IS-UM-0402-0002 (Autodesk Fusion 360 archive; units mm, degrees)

design "IS-UM-0402-0002" references "6 holes POWER", "LED", "3M Screw", "4 ports Ethernet", "SFP SLOT", "Digitus_DN-651107_LAN-Switch"
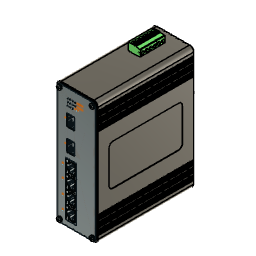
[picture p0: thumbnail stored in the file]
sketch "Sketch1" plane through (0, 0, 0) normal (0, 1, 0) x axis (1, 0, 0)
  line L1 (45, 0) -> (5, 0)
  line L2 (50, -145) -> (50, -5)
  line L3 (5, -150) -> (45, -150)
  line L4 (0, -5) -> (0, -145)
  arc A1 centre (5, -145) radius 5 clockwise from (5, -150) to (0, -145)
  arc A2 centre (45, -145) radius 5 clockwise from (50, -145) to (45, -150)
  arc A3 centre (5, -5) radius 5 clockwise from (0, -5) to (5, 0)
  arc A4 centre (45, -5) radius 5 clockwise from (45, 0) to (50, -5)
  point P1 (0, 0)
  point P2 (0, 0)
  point P4 (0, -150)
  point P3 (50, 0)
  horizontal L1
  vertical L2
  horizontal L3
  vertical L4
  coincident P1 P2
  coincident P4 L3
  coincident P4 L4
  tangent L3 A1
  tangent L4 A1
  tangent L2 A2
  tangent L3 A2
  equal A1 A2
  coincident P2 L1
  coincident P2 L4
  tangent L1 A3
  tangent L4 A3
  equal A1 A3
  coincident P3 L1
  coincident P3 L2
  tangent L1 A4
  tangent L2 A4
  equal A1 A4
  dimension "d1" distance P2 P3 = 50
  dimension "d2" distance P2 P4 = 150
  dimension "d3" radius A1 = 5
extrude "Extrude1" new body sketch "Sketch1" along normal blind 120
sketch "Sketch2" plane through (0, 0, 0) normal (0, -1, 0) x axis (1, 0, 0)
  line L1 (5, 150) -> (45, 150)
  line L2 (0, 5) -> (0, 145)
  line L3 (45, 0) -> (5, 0)
  line L4 (50, 145) -> (50, 5)
  line L5 (45, 1.5) -> (5, 1.5)
  line L6 (48.5, 145) -> (48.5, 5)
  line L7 (5, 148.5) -> (45, 148.5)
  line L8 (1.5, 5) -> (1.5, 145)
  line L9 (45, 0) -> (5, 0)
  line L10 (50, 145) -> (50, 5)
  line L11 (5, 150) -> (45, 150)
  line L12 (0, 5) -> (0, 145)
  arc A1 centre (45, 145) radius 5 clockwise from (45, 150) to (50, 145)
  arc A2 centre (5, 145) radius 5 clockwise from (0, 145) to (5, 150)
  arc A3 centre (5, 5) radius 5 clockwise from (5, 0) to (0, 5)
  arc A4 centre (45, 5) radius 5 clockwise from (50, 5) to (45, 0)
  arc A5 centre (45, 5) radius 3.5 clockwise from (48.5, 5) to (45, 1.5)
  arc A6 centre (45, 145) radius 3.5 clockwise from (45, 148.5) to (48.5, 145)
  arc A7 centre (5, 145) radius 3.5 clockwise from (1.5, 145) to (5, 148.5)
  arc A8 centre (5, 5) radius 3.5 clockwise from (5, 1.5) to (1.5, 5)
  arc A9 centre (45, 5) radius 5 clockwise from (50, 5) to (45, 0)
  arc A10 centre (45, 145) radius 5 clockwise from (45, 150) to (50, 145)
  arc A11 centre (5, 145) radius 5 clockwise from (0, 145) to (5, 150)
  arc A12 centre (5, 5) radius 5 clockwise from (5, 0) to (0, 5)
  dimension "d6" = -1.5
  dimension "d7" distance L3 = 0
extrude "Extrude2" cut sketch "Sketch2" against normal blind 1.5
sketch "Sketch3" plane through (0, 120, 0) normal (0, 1, 0) x axis (-1, 0, 0)
  line L1 (-50, 5) -> (-50, 145)
  line L2 (-5, 0) -> (-45, 0)
  line L3 (0, 145) -> (0, 5)
  line L4 (-45, 150) -> (-5, 150)
  line L5 (-5, 1.5) -> (-45, 1.5)
  line L6 (-1.5, 145) -> (-1.5, 5)
  line L7 (-45, 148.5) -> (-5, 148.5)
  line L8 (-48.5, 5) -> (-48.5, 145)
  line L9 (-5, 0) -> (-45, 0)
  line L10 (0, 145) -> (0, 5)
  line L11 (-45, 150) -> (-5, 150)
  line L12 (-50, 5) -> (-50, 145)
  arc A1 centre (-45, 145) radius 5 clockwise from (-50, 145) to (-45, 150)
  arc A2 centre (-45, 5) radius 5 clockwise from (-45, 0) to (-50, 5)
  arc A3 centre (-5, 5) radius 5 clockwise from (0, 5) to (-5, 0)
  arc A4 centre (-5, 145) radius 5 clockwise from (-5, 150) to (0, 145)
  arc A5 centre (-5, 5) radius 3.5 clockwise from (-1.5, 5) to (-5, 1.5)
  arc A6 centre (-5, 145) radius 3.5 clockwise from (-5, 148.5) to (-1.5, 145)
  arc A7 centre (-45, 145) radius 3.5 clockwise from (-48.5, 145) to (-45, 148.5)
  arc A8 centre (-45, 5) radius 3.5 clockwise from (-45, 1.5) to (-48.5, 5)
  arc A9 centre (-5, 5) radius 5 clockwise from (0, 5) to (-5, 0)
  arc A10 centre (-5, 145) radius 5 clockwise from (-5, 150) to (0, 145)
  arc A11 centre (-45, 145) radius 5 clockwise from (-50, 145) to (-45, 150)
  arc A12 centre (-45, 5) radius 5 clockwise from (-45, 0) to (-50, 5)
  dimension "d10" = -1.5
  dimension "d11" distance L2 = 0
extrude "Extrude3" cut sketch "Sketch3" against normal blind 1.5
sketch "Sketch4" plane through (0, 1.5, 0) normal (0, -1, 0) x axis (1, 0, 0)
  line L1 (1.5, 145) -> (1.5, 5)
  line L2 (45, 148.5) -> (5, 148.5)
  line L3 (48.5, 5) -> (48.5, 145)
  line L4 (5, 1.5) -> (45, 1.5)
  line L5 (45, 0) -> (5, 0)
  line L6 (50, 145) -> (50, 5)
  line L7 (5, 150) -> (45, 150)
  line L8 (0, 5) -> (0, 145)
  line L9 (25, 75) -> (25, 148.5)
  line L10 (25, 75) -> (1.5, 75)
  line L11 (0.75, 9) -> (0, 9)
  line L12 (0.75, 10.5) -> (0.75, 9)
  line L13 (0, 10.5) -> (0.75, 10.5)
  line L14 (0, 9) -> (0, 10.5)
  line L15 (0, 12.75) -> (0.75, 12.75)
  line L16 (0, 11.25) -> (0, 12.75)
  line L17 (0.75, 11.25) -> (0, 11.25)
  line L18 (0.75, 12.75) -> (0.75, 11.25)
  line L19 (0, 15) -> (0.75, 15)
  line L20 (0, 13.5) -> (0, 15)
  line L21 (0.75, 13.5) -> (0, 13.5)
  line L22 (0.75, 15) -> (0.75, 13.5)
  line L23 (0.75, 19.25) -> (0, 19.25)
  line L24 (0.75, 20.75) -> (0.75, 19.25)
  line L25 (0, 19.25) -> (0, 20.75)
  line L26 (0.75, 18.5) -> (0.75, 17)
  line L27 (0, 21.5) -> (0, 23)
  line L28 (0, 23) -> (0.75, 23)
  line L29 (0.75, 21.5) -> (0, 21.5)
  line L30 (0, 20.75) -> (0.75, 20.75)
  line L31 (0, 18.5) -> (0.75, 18.5)
  line L32 (0, 17) -> (0, 18.5)
  line L33 (0.75, 17) -> (0, 17)
  line L34 (0.75, 23) -> (0.75, 21.5)
  line L35 (0.75, 27.25) -> (0, 27.25)
  line L36 (0.75, 28.75) -> (0.75, 27.25)
  line L37 (0, 27.25) -> (0, 28.75)
  line L38 (0.75, 26.5) -> (0.75, 25)
  line L39 (0, 29.5) -> (0, 31)
  line L40 (0, 31) -> (0.75, 31)
  line L41 (0.75, 29.5) -> (0, 29.5)
  line L42 (0, 28.75) -> (0.75, 28.75)
  line L43 (0, 26.5) -> (0.75, 26.5)
  line L44 (0, 25) -> (0, 26.5)
  line L45 (0.75, 25) -> (0, 25)
  line L46 (0.75, 31) -> (0.75, 29.5)
  line L47 (0.75, 141) -> (0, 141)
  line L48 (0, 138.75) -> (0, 137.25)
  line L49 (0, 133) -> (0, 131.5)
  line L50 (0, 120.5) -> (0, 119)
  line L51 (0, 128.5) -> (0, 127)
  line L52 (0, 121.25) -> (0.75, 121.25)
  line L53 (0.75, 125) -> (0, 125)
  line L54 (0.75, 128.5) -> (0, 128.5)
  line L55 (0.75, 129.25) -> (0.75, 130.75)
  line L56 (0.75, 120.5) -> (0, 120.5)
  line L57 (0.75, 131.5) -> (0.75, 133)
  line L58 (0.75, 123.5) -> (0.75, 125)
  line L59 (0, 122.75) -> (0, 121.25)
  line L60 (0.75, 138.75) -> (0, 138.75)
  line L61 (0, 130.75) -> (0, 129.25)
  line L62 (0.75, 130.75) -> (0, 130.75)
  line L63 (0, 139.5) -> (0.75, 139.5)
  line L64 (0.75, 133) -> (0, 133)
  line L65 (0.75, 127) -> (0.75, 128.5)
  line L66 (0.75, 137.25) -> (0.75, 138.75)
  line L67 (0, 137.25) -> (0.75, 137.25)
  line L68 (0.75, 119) -> (0.75, 120.5)
  line L69 (0, 125) -> (0, 123.5)
  line L70 (0.75, 122.75) -> (0, 122.75)
  line L71 (0.75, 139.5) -> (0.75, 141)
  line L72 (0, 129.25) -> (0.75, 129.25)
  line L73 (0, 123.5) -> (0.75, 123.5)
  line L74 (0, 119) -> (0.75, 119)
  line L75 (0, 141) -> (0, 139.5)
  line L76 (0.75, 135) -> (0.75, 136.5)
  line L77 (0.75, 136.5) -> (0, 136.5)
  line L78 (0, 136.5) -> (0, 135)
  line L79 (0, 131.5) -> (0.75, 131.5)
  line L80 (0, 135) -> (0.75, 135)
  line L81 (0.75, 121.25) -> (0.75, 122.75)
  line L82 (0, 127) -> (0.75, 127)
  line L83 (49.25, 127) -> (49.25, 128.5)
  line L84 (50, 122.75) -> (50, 121.25)
  line L85 (49.25, 121.25) -> (49.25, 122.75)
  line L86 (50, 127) -> (49.25, 127)
  line L87 (49.25, 129.25) -> (49.25, 130.75)
  line L88 (49.25, 137.25) -> (49.25, 138.75)
  line L89 (50, 119) -> (49.25, 119)
  line L90 (50, 139.5) -> (49.25, 139.5)
  line L91 (50, 123.5) -> (49.25, 123.5)
  line L92 (50, 136.5) -> (50, 135)
  line L93 (50, 135) -> (49.25, 135)
  line L94 (50, 120.5) -> (50, 119)
  line L95 (50, 133) -> (50, 131.5)
  line L96 (49.25, 119) -> (49.25, 120.5)
  line L97 (50, 128.5) -> (50, 127)
  line L98 (49.25, 131.5) -> (49.25, 133)
  line L99 (49.25, 120.5) -> (50, 120.5)
  line L100 (49.25, 133) -> (50, 133)
  line L101 (50, 138.75) -> (50, 137.25)
  line L102 (50, 125) -> (50, 123.5)
  line L103 (49.25, 139.5) -> (49.25, 141)
  line L104 (49.25, 135) -> (49.25, 136.5)
  line L105 (49.25, 136.5) -> (50, 136.5)
  line L106 (50, 137.25) -> (49.25, 137.25)
  line L107 (49.25, 125) -> (50, 125)
  line L108 (50, 121.25) -> (49.25, 121.25)
  line L109 (49.25, 138.75) -> (50, 138.75)
  line L110 (50, 130.75) -> (50, 129.25)
  line L111 (49.25, 141) -> (50, 141)
  line L112 (49.25, 130.75) -> (50, 130.75)
  line L113 (50, 129.25) -> (49.25, 129.25)
  line L114 (50, 131.5) -> (49.25, 131.5)
  line L115 (49.25, 122.75) -> (50, 122.75)
  line L116 (50, 141) -> (50, 139.5)
  line L117 (49.25, 128.5) -> (50, 128.5)
  line L118 (49.25, 123.5) -> (49.25, 125)
  line L119 (50, 18.5) -> (49.25, 18.5)
  line L120 (49.25, 19.25) -> (50, 19.25)
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  point P22 (25, 148.5)
  point P23 (1.5, 75)
  point P25 (0, 9)
  point P74 (0, 141)
  point P26 (0.75, 9)
  point P81 (0.75, 141)
  point P27 (0.75, 10.5)
  point P77 (0.75, 139.5)
  point P28 (0, 10.5)
  point P69 (0, 139.5)
  point P29 (0.75, 12.75)
  point P67 (0.75, 137.25)
  point P30 (0, 12.75)
  point P68 (0, 137.25)
  point P31 (0, 11.25)
  point P89 (0, 138.75)
  point P32 (0.75, 11.25)
  point P86 (0.75, 138.75)
  point P33 (0.75, 15)
  point P79 (0.75, 135)
  point P34 (0, 15)
  point P94 (0, 135)
  point P35 (0, 13.5)
  point P90 (0, 136.5)
  point P36 (0.75, 13.5)
  point P65 (0.75, 136.5)
  point P37 (0.75, 17)
  point P95 (0.75, 133)
  point P38 (0, 19.25)
  point P96 (0, 130.75)
  point P39 (0.75, 19.25)
  point P75 (0.75, 130.75)
  point P40 (0.75, 20.75)
  point P72 (0.75, 129.25)
  point P41 (0.75, 23)
  point P73 (0.75, 127)
  point P42 (0, 20.75)
  point P62 (0, 129.25)
  point P43 (0, 23)
  point P61 (0, 127)
  point P44 (0.75, 18.5)
  point P63 (0.75, 131.5)
  point P45 (0, 21.5)
  point P66 (0, 128.5)
  point P46 (0, 17)
  point P70 (0, 133)
  point P47 (0.75, 21.5)
  point P91 (0.75, 128.5)
  point P48 (0, 18.5)
  point P84 (0, 131.5)
  point P49 (0.75, 25)
  point P83 (0.75, 125)
  point P50 (0, 27.25)
  point P76 (0, 122.75)
  point P51 (0.75, 27.25)
  point P78 (0.75, 122.75)
  point P52 (0.75, 28.75)
  point P88 (0.75, 121.25)
  point P53 (0.75, 31)
  point P87 (0.75, 119)
  point P54 (0, 28.75)
  point P82 (0, 121.25)
  point P55 (0, 31)
  point P80 (0, 119)
  point P56 (0.75, 26.5)
  point P85 (0.75, 123.5)
  point P57 (0, 29.5)
  point P93 (0, 120.5)
  point P58 (0, 25)
  point P92 (0, 125)
  point P59 (0.75, 29.5)
  point P71 (0.75, 120.5)
  point P60 (0, 26.5)
  point P64 (0, 123.5)
  point P5 (1.5, 145)
  point P123 (48.5, 145)
  point P21 (0, 145)
  point P106 (50, 145)
  point P145 (50, 9)
  point P140 (49.25, 9)
  point P158 (49.25, 10.5)
  point P153 (50, 10.5)
  point P166 (49.25, 12.75)
  point P170 (50, 12.75)
  point P169 (50, 11.25)
  point P167 (49.25, 11.25)
  point P151 (49.25, 15)
  point P152 (50, 15)
  point P154 (50, 13.5)
  point P161 (49.25, 13.5)
  point P143 (49.25, 17)
  point P141 (50, 19.25)
  point P137 (49.25, 19.25)
  point P160 (49.25, 20.75)
  point P155 (49.25, 23)
  point P156 (50, 20.75)
  point P162 (50, 23)
  point P159 (49.25, 18.5)
  point P148 (50, 21.5)
  point P149 (50, 17)
  point P147 (49.25, 21.5)
  point P165 (50, 18.5)
  point P168 (49.25, 25)
  point P150 (50, 27.25)
  point P157 (49.25, 27.25)
  point P163 (49.25, 28.75)
  point P164 (49.25, 31)
  point P144 (50, 28.75)
  point P136 (50, 31)
  point P146 (49.25, 26.5)
  point P139 (50, 29.5)
  point P142 (50, 25)
  point P138 (49.25, 29.5)
  point P135 (50, 26.5)
  point P97 (50, 127)
  point P100 (50, 129.25)
  point P98 (49.25, 131.5)
  point P99 (50, 123.5)
  point P105 (49.25, 136.5)
  point P114 (50, 128.5)
  point P103 (49.25, 137.25)
  point P102 (50, 137.25)
  point P101 (50, 139.5)
  point P110 (50, 133)
  point P115 (49.25, 120.5)
  point P111 (49.25, 129.25)
  point P112 (49.25, 127)
  point P104 (50, 141)
  point P113 (49.25, 130.75)
  point P132 (50, 122.75)
  point P109 (49.25, 139.5)
  point P131 (49.25, 122.75)
  point P108 (49.25, 135)
  point P134 (50, 119)
  point P117 (49.25, 141)
  point P133 (50, 121.25)
  point P130 (49.25, 125)
  point P124 (50, 131.5)
  point P125 (49.25, 123.5)
  point P121 (49.25, 138.75)
  point P127 (49.25, 119)
  point P128 (49.25, 121.25)
  point P118 (50, 138.75)
  point P120 (50, 136.5)
  point P122 (49.25, 128.5)
  point P119 (50, 125)
  point P116 (50, 120.5)
  point P126 (50, 135)
  point P107 (49.25, 133)
  point P129 (50, 130.75)
  midpoint L2 P22
  perpendicular L2 L9
  midpoint L1 P23
  perpendicular L9 L10
  horizontal L11
  vertical L12
  horizontal L13
  vertical L14
  coincident L8 P25
  symmetric L10 P25 P74
  symmetric L10 P26 P81
  symmetric L10 P27 P77
  symmetric L10 P28 P69
  symmetric L10 P29 P67
  symmetric L10 P30 P68
  symmetric L10 P31 P89
  symmetric L10 P32 P86
  symmetric L10 P33 P79
  symmetric L10 P34 P94
  symmetric L10 P35 P90
  symmetric L10 P36 P65
  symmetric L10 P37 P95
  symmetric L10 P38 P96
  symmetric L10 P39 P75
  symmetric L10 P40 P72
  symmetric L10 P41 P73
  symmetric L10 P42 P62
  symmetric L10 P43 P61
  symmetric L10 P44 P63
  symmetric L10 P45 P66
  symmetric L10 P46 P70
  symmetric L10 P47 P91
  symmetric L10 P48 P84
  symmetric L10 P49 P83
  symmetric L10 P50 P76
  symmetric L10 P51 P78
  symmetric L10 P52 P88
  symmetric L10 P53 P87
  symmetric L10 P54 P82
  symmetric L10 P55 P80
  symmetric L10 P56 P85
  symmetric L10 P57 P93
  symmetric L10 P58 P92
  symmetric L10 P59 P71
  symmetric L10 P60 P64
  symmetric P5 L9 P123
  symmetric P21 L9 P106
  symmetric L9 P25 P145
  symmetric L9 P26 P140
  symmetric L9 P27 P158
  symmetric L9 P28 P153
  symmetric L9 P29 P166
  symmetric L9 P30 P170
  symmetric L9 P31 P169
  symmetric L9 P32 P167
  symmetric L9 P33 P151
  symmetric L9 P34 P152
  symmetric L9 P35 P154
  symmetric L9 P36 P161
  symmetric L9 P37 P143
  symmetric L9 P38 P141
  symmetric L9 P39 P137
  symmetric L9 P40 P160
  symmetric L9 P41 P155
  symmetric L9 P42 P156
  symmetric L9 P43 P162
  symmetric L9 P44 P159
  symmetric L9 P45 P148
  symmetric L9 P46 P149
  symmetric L9 P47 P147
  symmetric L9 P48 P165
  symmetric L9 P49 P168
  symmetric L9 P50 P150
  symmetric L9 P51 P157
  symmetric L9 P52 P163
  symmetric L9 P53 P164
  symmetric L9 P54 P144
  symmetric L9 P55 P136
  symmetric L9 P56 P146
  symmetric L9 P57 P139
  symmetric L9 P58 P142
  symmetric L9 P59 P138
  symmetric L9 P60 P135
  symmetric L9 P61 P97
  symmetric L9 P62 P100
  symmetric L9 P63 P98
  symmetric L9 P64 P99
  symmetric L9 P65 P105
  symmetric L9 P66 P114
  symmetric L9 P67 P103
  symmetric L9 P68 P102
  symmetric L9 P69 P101
  symmetric L9 P70 P110
  symmetric L9 P71 P115
  symmetric L9 P72 P111
  symmetric L9 P73 P112
  symmetric L9 P74 P104
  symmetric L9 P75 P113
  symmetric L9 P76 P132
  symmetric L9 P77 P109
  symmetric L9 P78 P131
  symmetric L9 P79 P108
  symmetric L9 P80 P134
  symmetric L9 P81 P117
  symmetric L9 P82 P133
  symmetric L9 P83 P130
  symmetric L9 P84 P124
  symmetric L9 P85 P125
  symmetric L9 P86 P121
  symmetric L9 P87 P127
  symmetric L9 P88 P128
  symmetric L9 P89 P118
  symmetric L9 P90 P120
  symmetric L9 P91 P122
  symmetric L9 P92 P119
  symmetric L9 P93 P116
  symmetric L9 P94 P126
  symmetric L9 P95 P107
  symmetric L9 P96 P129
  dimension "d14" distance P25 P28 = 1.5
  dimension "d15" distance P27 P28 = 0.75
  dimension "d24" distance L10 L40 = 44
  dimension "d18" R-Pattern1-uDistance = 0
  dimension "d19" R-Pattern1-vDistance = 4.5
  dimension "d22" R-Pattern2-uDistance = 0
  dimension "d23" R-Pattern2-vDistance = 16
extrude "Extrude4" cut sketch "Sketch4" against normal blind 125
sketch "Sketch10" plane through (0, 0, 0) normal (0, -1, 0) x axis (1, 0, 0)
  line L1 (1.5, 5) -> (1.5, 145)
  line L2 (45, 1.5) -> (5, 1.5)
  line L3 (48.5, 145) -> (48.5, 5)
  line L4 (5, 148.5) -> (45, 148.5)
  line L5 (25, 75) -> (25, 148.5)
  line L6 (25, 75) -> (1.5, 75)
  line L7 (25, 73.5) -> (11.84, 73.5)
  line L8 (25, 7.89) -> (25, 73.5)
  line L9 (11.84, 7.89) -> (25, 7.89)
  line L10 (11.84, 73.5) -> (11.84, 7.89)
  line L11 (22.04, 80) -> (13.84, 80)
  line L12 (22.79, 93.75) -> (22.79, 80.75)
  line L13 (13.84, 94.5) -> (22.04, 94.5)
  line L14 (13.09, 80.75) -> (13.09, 93.75)
  line L15 (13.84, 121.5) -> (22.04, 121.5)
  line L16 (13.09, 107.75) -> (13.09, 120.75)
  line L17 (22.79, 120.75) -> (22.79, 107.75)
  line L18 (22.04, 107) -> (13.84, 107)
  arc A1 centre (5, 5) radius 3.5 clockwise from (5, 1.5) to (1.5, 5)
  arc A2 centre (45, 5) radius 3.5 clockwise from (48.5, 5) to (45, 1.5)
  arc A3 centre (45, 145) radius 3.5 clockwise from (45, 148.5) to (48.5, 145)
  arc A4 centre (5, 145) radius 3.5 clockwise from (1.5, 145) to (5, 148.5)
  arc A5 centre (13.84, 80.75) radius 0.75 clockwise from (13.84, 80) to (13.09, 80.75)
  arc A6 centre (22.04, 80.75) radius 0.75 clockwise from (22.79, 80.75) to (22.04, 80)
  arc A7 centre (22.04, 93.75) radius 0.75 clockwise from (22.04, 94.5) to (22.79, 93.75)
  arc A8 centre (13.84, 93.75) radius 0.75 clockwise from (13.09, 93.75) to (13.84, 94.5)
  arc A9 centre (22.04, 120.75) radius 0.75 clockwise from (22.04, 121.5) to (22.79, 120.75)
  arc A10 centre (13.84, 120.75) radius 0.75 clockwise from (13.09, 120.75) to (13.84, 121.5)
  arc A11 centre (13.84, 107.75) radius 0.75 clockwise from (13.84, 107) to (13.09, 107.75)
  arc A12 centre (22.04, 107.75) radius 0.75 clockwise from (22.79, 107.75) to (22.04, 107)
  circle C1 centre (14.59, 129.5) radius 0.75
  circle C2 centre (17.59, 129.5) radius 0.75
  circle C3 centre (20.59, 129.5) radius 0.75
  circle C4 centre (14.59, 133.5) radius 0.75
  circle C5 centre (17.59, 133.5) radius 0.75
  circle C6 centre (20.59, 133.5) radius 0.75
  circle C7 centre (14.59, 137.5) radius 0.75
  circle C8 centre (17.59, 137.5) radius 0.75
  circle C9 centre (20.59, 137.5) radius 0.75
  circle C10 centre (23.59, 137.5) radius 0.75
  circle C11 centre (23.59, 133.5) radius 0.75
  circle C12 centre (5, 145) radius 1.5
  circle C13 centre (45, 145) radius 1.5
  circle C14 centre (5, 5) radius 1.5
  circle C15 centre (45, 5) radius 1.5
  point P14 (25, 148.5)
  point P15 (1.5, 75)
  point P21 (13.09, 80)
  point P22 (22.79, 94.5)
  point P23 (13.09, 94.5)
  point P18 (25, 73.5)
  point P19 (25, 7.89)
  point P20 (11.84, 7.89)
  point P48 (14.59, 129.5)
  midpoint L4 P14
  perpendicular L4 L5
  midpoint L1 P15
  perpendicular L5 L6
  horizontal L7
  vertical L8
  horizontal L9
  vertical L10
  collinear L5 L8
  horizontal L11
  vertical L12
  horizontal L13
  vertical L14
  coincident P21 L11
  coincident P21 L14
  tangent L11 A5
  tangent L14 A5
  tangent L11 A6
  tangent L12 A6
  equal A5 A6
  coincident P22 L12
  coincident P22 L13
  tangent L12 A7
  tangent L13 A7
  equal A5 A7
  coincident P23 L13
  coincident P23 L14
  tangent L13 A8
  tangent L14 A8
  equal A5 A8
  concentric A4 C12
  dimension "d142" distance P18 P19 = 65.61
  dimension "d143" distance P19 P20 = 13.16
  dimension "d144" distance L6 L7 = 1.5
  dimension "d145" distance P21 P23 = 14.5
  dimension "d146" distance P22 P23 = 9.7
  dimension "d147" radius A5 = 0.75
  dimension "d148" distance L6 L11 = 5
  dimension "d149" distance L10 L14 = 1.25
  dimension "d154" diameter C1 = 1.5
  dimension "d155" distance L15 P48 = 8
  dimension "d156" distance L16 P48 = 1.5
  dimension "d169" diameter C12 = 3
  dimension "d152" R-Pattern1-uDistance = 0
  dimension "d153" R-Pattern1-vDistance = 27
  dimension "d159" R-Pattern2-uDistance = 6
  dimension "d160" R-Pattern2-vDistance = 0
  dimension "d163" R-Pattern3-uDistance = 0
  dimension "d164" R-Pattern3-vDistance = 8
  dimension "d167" R-Pattern4-uDistance = 3
  dimension "d168" R-Pattern4-vDistance = 0
  dimension "d172" R-Pattern5-uDistance = 40
  dimension "d173" R-Pattern5-vDistance = 0
  dimension "d176" R-Pattern6-uDistance = 0
  dimension "d177" R-Pattern6-vDistance = -140
extrude "Extrude8" cut sketch "Sketch10" profile of L7 L8 L9 L10 L11 L12 L13 L14 A5 A6 A7 A8 L15 A9 A10 L16 L17 A11 L18 A12 C1 C2 C3 C4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 against normal blind 3
shell "Shell2" innerThickness 1
sketch "Sketch11" plane through (0, 0, 150) normal (0, 0, 1) x axis (-1, 0, 0)
  line L1 (-5, -118.5) -> (-45, -118.5)
  line L2 (-5, -1.5) -> (-5, -118.5)
  line L3 (-45, -1.5) -> (-5, -1.5)
  line L4 (-45, -118.5) -> (-45, -1.5)
  line L5 (-25, -60) -> (-25, -118.5)
  line L6 (-25, -60) -> (-5, -60)
  line L7 (-22, -105) -> (-13.4, -105)
  line L8 (-22, -75) -> (-22, -105)
  line L9 (-13.4, -75) -> (-22, -75)
  line L10 (-13.4, -105) -> (-13.4, -75)
  point P6 (-25, -118.5)
  point P7 (-5, -60)
  point P9 (-13.4, -105)
  point P12 (-13.4, -75)
  point P10 (-22, -105)
  midpoint L1 P6
  perpendicular L1 L5
  midpoint L2 P7
  perpendicular L2 L6
  horizontal L7
  vertical L8
  horizontal L9
  vertical L10
  dimension "d181" distance P9 P12 = 30
  dimension "d182" distance P9 P10 = 8.6
  dimension "d183" distance L5 L8 = 3
  dimension "d184" distance L6 L9 = 15
extrude "Extrude9" cut sketch "Sketch11" profile of L7 L8 L9 L10 against normal blind 5
component_insert "Component Insert1"
joint "Assemble3" alignAngle 0 alignOffsetX 0 alignOffsetY 0 alignOffsetZ 2.5
rectangular_pattern "00000000-0000-0000-0000-000000000000" uSpaceDistance 6 vSpaceDistance 0
rectangular_pattern "00000000-0000-0000-0000-000000000000" uSpaceDistance 8 vSpaceDistance 0
rectangular_pattern "00000000-0000-0000-0000-000000000000" uSpaceDistance 3 vSpaceDistance 0
component_insert "Component Insert4"
joint "Assemble4" alignAngle -90 alignOffsetX 0 alignOffsetY 0 alignOffsetZ 6
rectangular_pattern "00000000-0000-0000-0000-000000000000" uSpaceDistance 40 vSpaceDistance 0
rectangular_pattern "00000000-0000-0000-0000-000000000000" uSpaceDistance -140 vSpaceDistance 0
component_insert "Component Insert7"
position "Position2"
component_insert "Component Insert10"
decal "Decal1"
sketch "Sketch9" plane through (50, 0, 0) normal (1, 0, 0) x axis (0, 1, 0)
  line L1 (118.5, 31) -> (1.5, 31)
  line L2 (118.5, 119) -> (118.5, 31)
  line L3 (1.5, 119) -> (118.5, 119)
  line L4 (1.5, 31) -> (1.5, 119)
  line L5 (60, 75) -> (60, 119)
  line L6 (60, 75) -> (1.5, 75)
  line L7 (100, 100) -> (20, 100)
  line L8 (105, 55) -> (105, 95)
  line L9 (20, 50) -> (100, 50)
  line L10 (15, 95) -> (15, 55)
  arc A1 centre (20, 55) radius 5 clockwise from (20, 50) to (15, 55)
  arc A2 centre (100, 55) radius 5 clockwise from (105, 55) to (100, 50)
  arc A3 centre (100, 95) radius 5 clockwise from (100, 100) to (105, 95)
  arc A4 centre (20, 95) radius 5 clockwise from (15, 95) to (20, 100)
  point P6 (60, 119)
  point P7 (1.5, 75)
  point P11 (15, 50)
  point P10 (105, 50)
  point P9 (15, 100)
  midpoint L3 P6
  perpendicular L3 L5
  midpoint L4 P7
  perpendicular L4 L6
  horizontal L7
  vertical L8
  horizontal L9
  vertical L10
  symmetric L6 L7 L9
  coincident P11 L9
  coincident P11 L10
  tangent L9 A1
  tangent L10 A1
  coincident P10 L8
  coincident P10 L9
  tangent L8 A2
  tangent L9 A2
  equal A1 A2
  tangent L7 A3
  tangent L8 A3
  equal A1 A3
  coincident P9 L7
  coincident P9 L10
  tangent L7 A4
  tangent L10 A4
  equal A1 A4
  dimension "d137" distance P9 P11 = 50
  dimension "d138" distance P10 P11 = 90
  dimension "d139" radius A1 = 5
extrude "Extrude7" cut sketch "Sketch9" profile of L5 L6 L7 L8 L9 L10 A1 A2 A3 A4 against normal blind 0.5
component_insert "Component Insert11"
position "Position4"
rectangular_pattern "00000000-0000-0000-0000-000000000000" uSpaceDistance -27 vSpaceDistance 0
component_insert "Component Insert12"
position "Position5"
sketch "Sketch12" plane through (0, 0, 0) normal (0, -1, 0) x axis (1, 0, 0)
  dimension "d211" = 1
  dimension "d212" = 1
  dimension "d213" = 1
  dimension "d214" = 1
  dimension "d215" = 1
  dimension "d216" = 1
  dimension "d217" = 1
  dimension "d218" = 1
  dimension "d219" = 1
  dimension "d220" = 1
  dimension "d221" = 1
  dimension "d222" = 1
  dimension "d223" = 1
  dimension "d224" = 2
  dimension "d225" = 2
  dimension "d226" = 2
  dimension "d227" = 2
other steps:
joint_origin "JointOrigin3"
joint_origin "JointOrigin4"

design "LED"
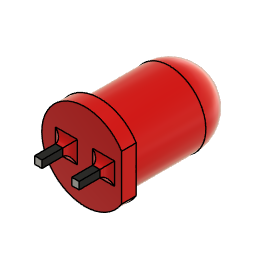
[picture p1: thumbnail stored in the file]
description: STEP AP214
part number: LED

design "6 holes POWER"
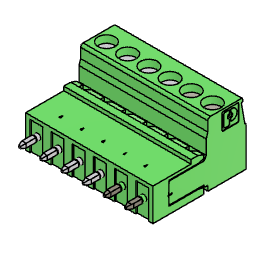
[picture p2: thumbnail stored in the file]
description: STEP AP214
part number: POWER

design "3M Screw"
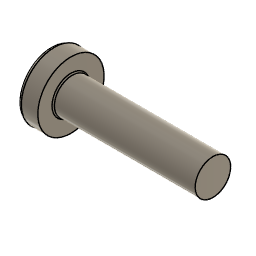
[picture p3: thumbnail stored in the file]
description: STEP AP214
part number: 3M Screw

design "SFP SLOT"
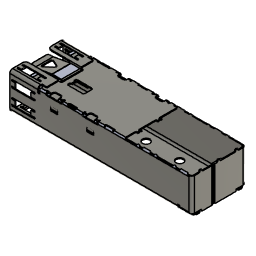
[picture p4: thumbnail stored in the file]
description: STEP AP214
part number: SFP SLOT

design "4 ports Ethernet"
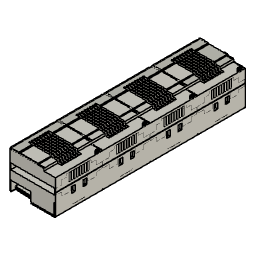
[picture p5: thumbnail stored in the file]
description: STEP AP214
part number: 4 ports Ethernet

design "Digitus_DN-651107_LAN-Switch"
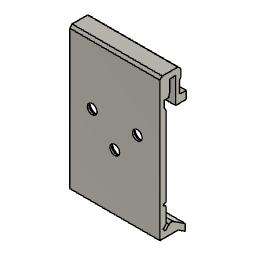
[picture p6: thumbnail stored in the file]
description: STEP AP214
part number: Digitus_DN-651107_LAN-Switch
